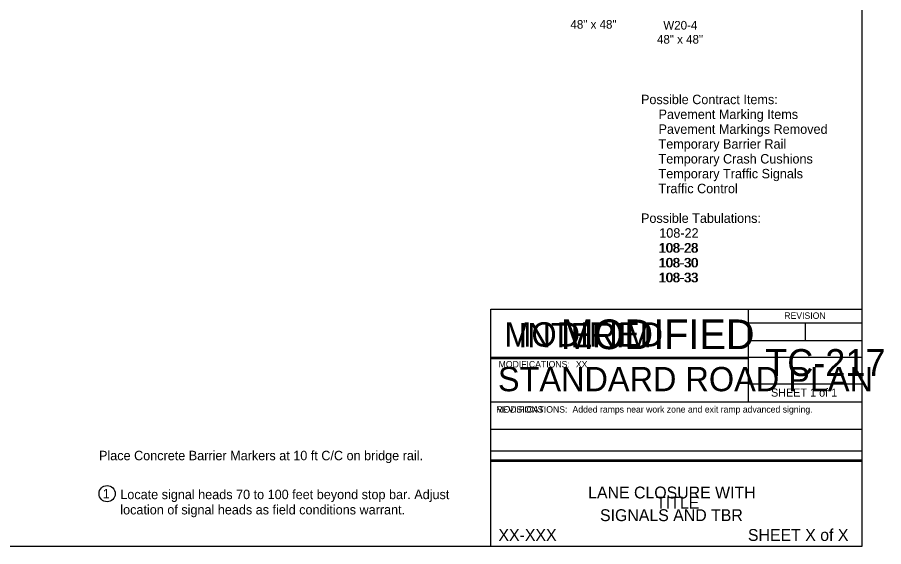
# Model space of a CAD drawing. Extents: x -2134934 to -2122394, y -2140205 to -2137036.
# Drawn here: x -2133366 to -2131759, y -2139046 to -2138065 of the extents above; entities that cross this region are included whole.
import ezdxf

# ---------------------------------------------------------------- set-up
doc = ezdxf.new("R2010")
doc.units = 0
for name, color, linetype in [('Barrier', 7, 'Continuous'), ('BridgeSuperStructureExisting', 7, 'Continuous'), ('Default', 7, 'Continuous'), ('Dimension', 7, 'Continuous'), ('dsnAlignmentCurveData', 7, 'Continuous'), ('dsnAlignmentTic', 7, 'Continuous'), ('dsnCellElements', 7, 'Continuous'), ('DsnShtOutsideBorder', 7, 'Continuous'), ('hwyPlanSheetShape', 7, 'Continuous')]:
    doc.layers.add(name, color=color, linetype=linetype)

msp = doc.modelspace()

# ---------------------------------------------------------------- linework, layer by layer
at = {"layer": 'BridgeSuperStructureExisting'}
msp.add_circle((-2133199.2, -2138947.8), 15, dxfattribs=at)
at = {"layer": 'Default'}
msp.add_lwpolyline([(-2134934.4, -2137035.9), (-2131799.4, -2137035.9), (-2131799.4, -2139045.9), (-2134934.4, -2139045.9)], close=True, dxfattribs=at)
at = {"layer": 'Dimension'}
for p, q in [((-2132010.4, -2138605.9), (-2132010.4, -2138697.3)), ((-2132010.4, -2138630.9), (-2131799.4, -2138630.9)), ((-2131904.9, -2138630.9), (-2131904.9, -2138664.1)), ((-2132010.4, -2138664.1), (-2131799.4, -2138664.1)), ((-2132487.5, -2138697.3), (-2132010.4, -2138697.3)), ((-2132010.4, -2138697.3), (-2132010.4, -2138777.3)), ((-2131799.4, -2138745.1), (-2132010.4, -2138745.1)), ((-2132487.5, -2138777.3), (-2131799.4, -2138777.3)), ((-2132487.5, -2138828.3), (-2131799.4, -2138828.3)), ((-2132487.5, -2138868.3), (-2131799.4, -2138868.3)), ((-2132487.5, -2138887.3), (-2131799.4, -2138887.3))]:
    msp.add_line(p, q, dxfattribs=at)
msp.add_lwpolyline([(-2132487.5, -2138605.9), (-2131799.4, -2138605.9), (-2131799.4, -2139045.9), (-2132487.5, -2139045.9)], close=True, dxfattribs=at)
at = {"layer": 'DsnShtOutsideBorder'}
for p, q in [((-2132487.5, -2138695), (-2131799.4, -2138695)), ((-2132487.5, -2138885), (-2131799.4, -2138885))]:
    msp.add_line(p, q, dxfattribs=at)
msp.add_lwpolyline([(-2132487.5, -2138605.9), (-2131799.4, -2138605.9), (-2131799.4, -2139045.9), (-2132487.5, -2139045.9)], close=True, dxfattribs=at)

# ---------------------------------------------------------------- texts
at = {"layer": 'Barrier'}
for s, p in [('48" x 48"', (-2132339.9, -2138086)), ('W20-4', (-2132167.7, -2138087.7)), ('48" x 48"', (-2132179.4, -2138113.7))]:
    msp.add_text(s, height=16, dxfattribs=at).set_placement(p)
at = {"layer": 'BridgeSuperStructureExisting'}
for s, p in [('1', (-2133207.3, -2138956.6)), ('Locate signal heads 70 to 100 feet beyond stop bar. Adjust ', (-2133174.7, -2138957.9)), ('location of signal heads as field conditions warrant.', (-2133174.7, -2138986.2))]:
    msp.add_text(s, height=17.5, dxfattribs=at).set_placement(p)
at = {"layer": 'Dimension'}
for s, height, p in [('REVISION', 12, (-2131943.4, -2138623.8)), ('TC-217', 50, (-2131978.7, -2138729.8)), ('STANDARD ROAD PLAN', 45.001, (-2132474.4, -2138757.9)), ('SHEET 1 of 1', 15, (-2131968, -2138767.9)), ('Added ramps near work zone and exit ramp advanced signing.', 12, (-2132336.1, -2138797.5)), ('LANE CLOSURE WITH', 22, (-2132307.1, -2138956.6)), ('SIGNALS AND TBR', 22, (-2132285.1, -2138998.6))]:
    msp.add_text(s, height=height, dxfattribs=at).set_placement(p)
at = {"layer": 'dsnAlignmentCurveData'}
msp.add_text('REVISIONS:', height=12, dxfattribs=at).set_placement((-2132477.5, -2138797.6))
at = {"layer": 'dsnAlignmentTic'}
for s, height, p in [('MODIFIED', 45, (-2132462.4, -2138675.1)), ('MODIFICATIONS:', 12, (-2132477.5, -2138797.6))]:
    msp.add_text(s, height=height, dxfattribs=at).set_placement(p)
at = {"layer": 'dsnCellElements'}
for s, p in [('Possible Contract Items:', (-2132209.1, -2138225.9)), ('     Pavement Marking Items', (-2132209.1, -2138253.4)), ('     Pavement Markings Removed', (-2132209.1, -2138280.9)), ('     Temporary Barrier Rail', (-2132209.1, -2138308.4)), ('     Temporary Crash Cushions', (-2132209.1, -2138335.9)), ('     Temporary Traffic Signals', (-2132209.1, -2138363.4)), ('     Traffic Control', (-2132209.1, -2138390.9)), ('Possible Tabulations:', (-2132209.1, -2138445.9)), ('108-22', (-2132175.2, -2138473.3)), ('108-22', (-2132175.2, -2138473.4)), ('     108-28', (-2132209.1, -2138500.9)), ('108-28', (-2132175.2, -2138500.9)), ('     108-30', (-2132209.1, -2138528.4)), ('108-30', (-2132175.2, -2138528.4)), ('     108-33', (-2132209.1, -2138555.9)), ('108-33', (-2132175.2, -2138555.9)), ('Place Concrete Barrier Markers at 10 ft C/C on bridge rail.', (-2133214.2, -2138885.8))]:
    msp.add_text(s, height=17.5, dxfattribs=at).set_placement(p)
at = {"layer": 'DsnShtOutsideBorder'}
for s, height, p in [('MODIFIED', 55, (-2132358.1, -2138679.9)), ('MODIFICATIONS:', 12, (-2132473.1, -2138713.9)), ('XX', 12, (-2132329.9, -2138713.9)), ('TITLE', 22, (-2132181.1, -2138975.4)), ('XX-XXX', 22, (-2132473.5, -2139035.3)), ('SHEET X of X', 22, (-2132010.8, -2139035.3))]:
    msp.add_text(s, height=height, dxfattribs=at).set_placement(p)
at = {"layer": 'hwyPlanSheetShape'}
msp.add_text('INTERIM', height=45, dxfattribs=at).set_placement((-2132436.5, -2138676.3))

doc.saveas('drawing.dxf')
